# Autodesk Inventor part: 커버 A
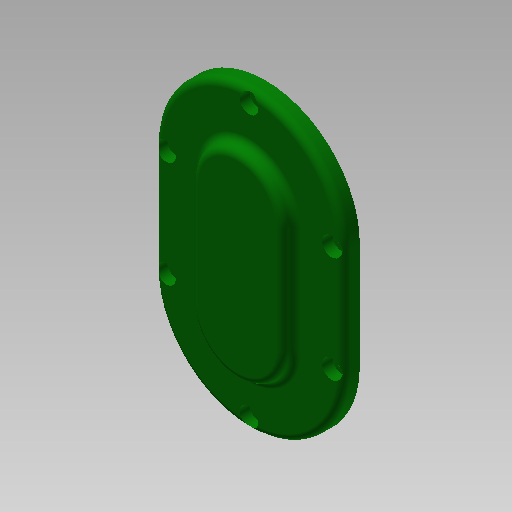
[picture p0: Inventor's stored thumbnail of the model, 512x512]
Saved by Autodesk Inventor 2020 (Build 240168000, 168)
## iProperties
Created: 2020-04
Part Number: 커버 A
Material: 알루미늄 6061
Document SubType Name: Modeling
Designer: mduedu
Density: 2.71 g/cm^3
Mass: 216.973 g
Surface Area: 231.179 cm^2
Volume: 80.0638 cm^3
Appearance: 진녹색
Author: mduedu
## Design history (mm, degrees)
sketch "스케치1"
  geometry: L1 (-40, 0)-(-40, -45); L2 (40, 0)-(40, -45); A1 r 40 centre (0, 0) between (40, 0) and (-40, 0); A2 r 40 centre (0, -45) between (-40, -45) and (40, -45); 1 further point
  constraints: 4 end point, 4 point on circle, 4 tangent, 2 centre point, 1 coincident, 1 equal radius, 1 vertical alignment
  dimensions: "d0" = 80 diameter of A1; "d31" = 45 distance of point (0, 0) A2.centre
extrude "돌출1" new body sketch "스케치1" distance "d1" = 7; taper "d2" = 0 deg
fillet "모깎기2" dims "d7" = 3
sketch "스케치4"
  geometry: L1 (30, 0)-(30, -45); L2 (-30, 0)-(-30, -45); A1 r 30 centre (0, 0) between (30, 0) and (-30, 0); A2 r 30 centre (0, -45) between (-30, -45) and (30, -45); 1 further point
  constraints: 4 end point, 4 point on circle, 4 tangent, 2 centre point, 1 coincident, 1 equal radius, 1 vertical alignment
  dimensions: "d19" = 60 diameter of A1; "d38" = 45 distance of point (0, 0) A2.centre
extrude "돌출3" join sketch "스케치4" distance "d20" = 4; taper "d21" = 0 deg
sketch "스케치7"
  geometry: L1 (-20, 0)-(-20, -45); L2 (20, 0)-(20, -45); A1 r 20 centre (0, 0) between (20, 0) and (-20, 0); A2 r 20 centre (0, -45) between (-20, -45) and (20, -45); 1 further point
  constraints: 4 end point, 4 point on circle, 4 tangent, 2 centre point, 1 coincident, 1 equal radius, 1 vertical alignment
  dimensions: "d45" = 40 diameter of A1; "d47" = 45 distance of point (0, 0) A2.centre
extrude "돌출5" join sketch "스케치7" distance "d48" = 5; taper "d49" = -15 deg
fillet "모깎기4" dims "d50" = 3
chamfer "모따기2" distance "d58" = 1; stored, may be unused: second distance "d59" = 2, angle "d60" = 45 deg
sketch "스케치6"
  geometry: L1 (0, 7)-(37, 7) reference; L2 (0, -4)-(30, -4) reference; L3 (0, -4)-(0, 8); L4 (0, 8)-(8, 8); L5 (11, 5)-(11, 5); L6 (11, 5)-(16, 5); L7 (16, 5)-(16, -4); L8 (-45, -4)-(-45, 8); L9 (-45, 8)-(-37, 8); L10 (-34, 5)-(-34, 4); L11 (-34, 4)-(-31, 4); L12 (-31, 4)-(-31, -4); L13 (-31, -4)-(-45, -4); A1 r 3 centre (8, 5) between (11, 5) and (8, 8); A2 r 3 centre (-37, 5) between (-34, 5) and (-37, 8); 3 further points
  constraints: 22 end point, 5 parallel, 5 point on line, 4 perpendicular, 4 point on circle, 4 tangent, 2 centre point, 2 horizontal alignment, 1 horizontal, 1 vertical
  dimensions: "d39" = 32 diameter of L7 L3; "d41" = 3 distance of point (11, 8) L5.end; "d42" = 9 distance of L6.end L7.end; "d43" = 22 diameter of L5 L3; "d44" = 3 radius of A1; "d51" = 8 distance of L11.end L12.end; "d52" = 45 distance of L2.start L8.start; "d53" = 28 diameter of L12 L8; "d54" = 22 diameter of L10 L8; "d55" = 3 radius of A2
revolve "회전1" stored, may be unused: angle "d56" = 90 deg
revolve "회전2" stored, may be unused: angle "d57" = 90 deg
sketch "스케치3"
  geometry: A1 r 35 centre (0, 0) between (0, 35) and (-35, 0); A2 r 35 centre (0, -45) between (-35, -45) and (0, -80); 3 further points
  constraints: 6 point on circle, 5 vertical alignment, 2 centre point, 2 horizontal alignment, 1 coincident, 1 equal radius
  dimensions: "d8" = 70 diameter of A1; "d69" = 45 distance of point (0, 0) A2.centre
hole "구멍1" sketch "스케치3" at (0, 35), (-35, 0), (-35, -45), (0, -80), (35, -45), (35, 0) diameter "d9" = 4.5; stored, may be unused: countersink angle "d13" = 90 deg, drill point angle "d15" = 118 deg; dims "d10" = 6, "d11" = 8, "d12" = 4.4, "d14" = 8
fillet "모깎기5" dims "d70" = 0.3
chamfer "모따기3" distance "d71" = 1; stored, may be unused: second distance "d72" = 2, angle "d73" = 45 deg
node "솔리드1"
